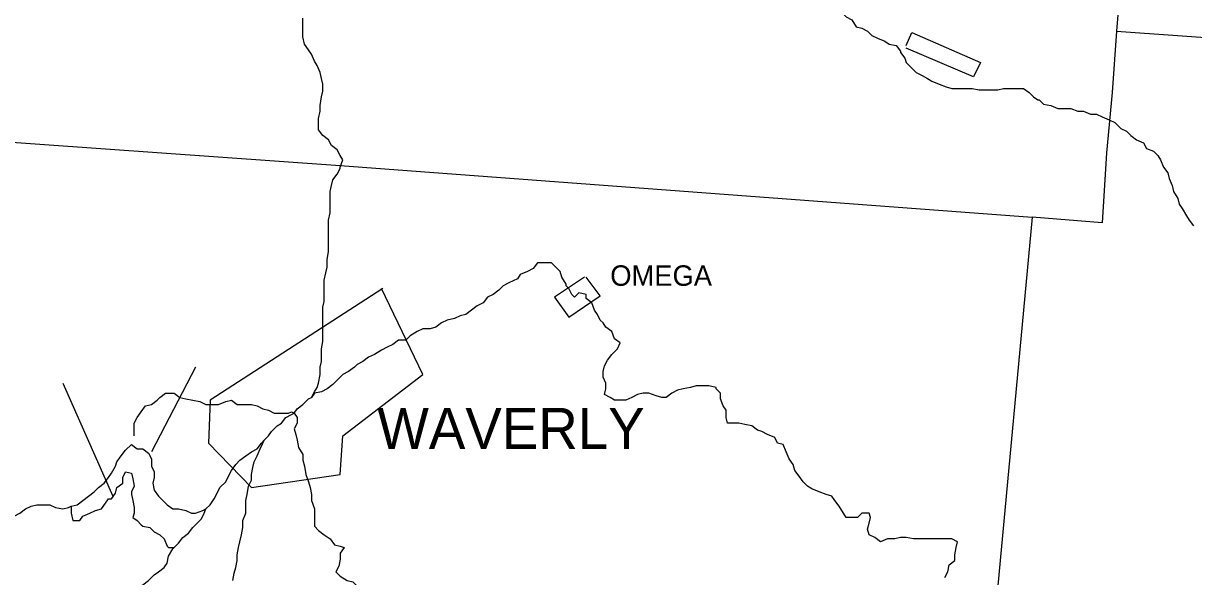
# Model space of a CAD drawing. Extents: x 0 to 34, y 0 to 22.
# Drawn here: x 5.85 to 6.966, y 18.089 to 18.617 of the extents above; entities that cross this region are included whole.
import ezdxf

# ---------------------------------------------------------------- set-up
doc = ezdxf.new("R2010")
doc.units = 0
doc.layers.add('Default', color=7, linetype='Continuous')

msp = doc.modelspace()

# ---------------------------------------------------------------- linework, layer by layer
at = {"layer": 'Default'}
for p, q in [((6.0144, 18.2889), (5.9722, 18.2085)), ((5.8876, 18.2739), (5.9354, 18.1662))]:
    msp.add_line(p, q, dxfattribs=at)
for points in [[(6.9566, 19.5337), (6.9457, 19.3646), (6.9197, 18.9774), (6.9088, 18.8056), (6.8925, 18.6093)], [(6.6048, 18.6529), (6.6089, 18.6475), (6.6143, 18.6448), (6.6184, 18.6379), (6.6212, 18.6339), (6.6266, 18.6339), (6.6307, 18.627), (6.6348, 18.6229), (6.6402, 18.6202), (6.6443, 18.6134), (6.6498, 18.612), (6.6552, 18.6093), (6.6593, 18.6052), (6.6648, 18.6025), (6.6716, 18.5998), (6.6757, 18.597), (6.6825, 18.5957), (6.6866, 18.5902), (6.6866, 18.5889)], [(6.1521, 18.4798), (6.1549, 18.4866), (6.1521, 18.4907), (6.1494, 18.4961), (6.144, 18.5002), (6.1412, 18.5057), (6.1358, 18.5098), (6.1317, 18.5152), (6.1317, 18.5207), (6.1317, 18.5261), (6.1331, 18.533), (6.1331, 18.5384), (6.1344, 18.5466), (6.1358, 18.552), (6.1358, 18.5589), (6.1344, 18.5643), (6.1331, 18.5698), (6.1303, 18.5766), (6.1276, 18.5807), (6.1249, 18.5875), (6.1221, 18.5916), (6.1181, 18.597), (6.1167, 18.6039), (6.1167, 18.6093), (6.1167, 18.6161), (6.1167, 18.6216)], [(6.1521, 18.4798), (6.1549, 18.4866), (6.1521, 18.4907), (6.1494, 18.4961), (6.144, 18.5002), (6.1412, 18.5057), (6.1358, 18.5098), (6.1317, 18.5152), (6.1317, 18.5207), (6.1317, 18.5261), (6.1331, 18.533), (6.1331, 18.5384), (6.1344, 18.5466), (6.1358, 18.552), (6.1358, 18.5589), (6.1344, 18.5643), (6.1331, 18.5698), (6.1303, 18.5766), (6.1276, 18.5807), (6.1249, 18.5875), (6.1221, 18.5916), (6.1181, 18.597), (6.1167, 18.6039), (6.1167, 18.6093), (6.1167, 18.6161), (6.1167, 18.6216)], [(6.6921, 18.5957), (6.6975, 18.6079), (6.763, 18.5793), (6.7561, 18.5657), (6.6921, 18.593)], [(6.8925, 18.6093), (6.8925, 18.6093), (6.8884, 18.5507), (6.8829, 18.4934), (6.8788, 18.4266), (6.812, 18.4321)], [(6.8925, 18.6093), (7.067, 18.597), (7.142, 18.593), (7.1761, 18.5902), (7.2892, 18.5834), (7.2838, 18.5261), (7.322, 18.5221), (7.3629, 18.5152), (7.4188, 18.5071), (7.4501, 18.5057), (7.5074, 18.5057), (7.5606, 18.5057), (7.6096, 18.4975), (7.6887, 18.4866), (7.6764, 18.3203)], [(6.6866, 18.5889), (6.6907, 18.5834), (6.6921, 18.5793), (6.6975, 18.5739), (6.7016, 18.5698), (6.7071, 18.567), (6.7125, 18.5643), (6.7166, 18.5616), (6.7234, 18.5589), (6.7302, 18.5561), (6.7357, 18.5548), (6.7411, 18.5548), (6.748, 18.5548), (6.7548, 18.5548), (6.7616, 18.5534), (6.7657, 18.5534), (6.7725, 18.5534), (6.7793, 18.5534), (6.7848, 18.5548), (6.7902, 18.5548), (6.7984, 18.5548), (6.8039, 18.5548), (6.8093, 18.5507), (6.8134, 18.5466), (6.8175, 18.5439), (6.8189, 18.5439)], [(4.8119, 18.5752), (4.9496, 18.567), (5.5209, 18.5261), (6.1521, 18.4811), (6.812, 18.4321)], [(6.8189, 18.5439), (6.8229, 18.5398), (6.8298, 18.5384), (6.8366, 18.5357), (6.842, 18.5357), (6.8489, 18.5357), (6.8557, 18.533), (6.8611, 18.533), (6.8679, 18.5302), (6.8734, 18.5302), (6.8788, 18.5275), (6.8857, 18.5248), (6.8857, 18.5248)], [(6.8857, 18.5248), (6.8911, 18.5221), (6.8966, 18.5166), (6.902, 18.5139), (6.9061, 18.5098), (6.9116, 18.5057), (6.9184, 18.503), (6.9211, 18.4975), (6.9279, 18.4948), (6.932, 18.4907), (6.9347, 18.4866), (6.9375, 18.4798), (6.9416, 18.4743), (6.9429, 18.4689), (6.9457, 18.4621), (6.947, 18.4566), (6.9511, 18.4498), (6.9525, 18.4443), (6.9552, 18.4402), (6.9593, 18.4334), (6.962, 18.4293), (6.9661, 18.4239)], [(6.1249, 18.2603), (6.1276, 18.2657), (6.1303, 18.2698), (6.1317, 18.2739), (6.1331, 18.2821), (6.1331, 18.2889), (6.1344, 18.2944), (6.1344, 18.3012), (6.1344, 18.3066), (6.1358, 18.3134), (6.1358, 18.3203), (6.1358, 18.3257), (6.1358, 18.3339), (6.1358, 18.3394), (6.1358, 18.3462), (6.1371, 18.3516), (6.1371, 18.3584), (6.1371, 18.3639), (6.1371, 18.3721), (6.1385, 18.3789), (6.1399, 18.3843), (6.1399, 18.3912), (6.1412, 18.3993), (6.1412, 18.4048), (6.1412, 18.4116), (6.1412, 18.4171), (6.1412, 18.4239), (6.1412, 18.4293), (6.1426, 18.4362), (6.1426, 18.443), (6.1426, 18.4498), (6.1426, 18.4566), (6.144, 18.4621), (6.1453, 18.4675), (6.1494, 18.473), (6.1521, 18.4784), (6.1521, 18.4784), (6.1521, 18.4798)], [(6.1249, 18.2603), (6.1276, 18.2657), (6.1303, 18.2698), (6.1317, 18.2739), (6.1331, 18.2821), (6.1331, 18.2889), (6.1344, 18.2944), (6.1344, 18.3012), (6.1344, 18.3066), (6.1358, 18.3134), (6.1358, 18.3203), (6.1358, 18.3257), (6.1358, 18.3339), (6.1358, 18.3394), (6.1358, 18.3462), (6.1371, 18.3516), (6.1371, 18.3584), (6.1371, 18.3639), (6.1371, 18.3721), (6.1385, 18.3789), (6.1399, 18.3843), (6.1399, 18.3912), (6.1412, 18.3993), (6.1412, 18.4048), (6.1412, 18.4116), (6.1412, 18.4171), (6.1412, 18.4239), (6.1412, 18.4293), (6.1426, 18.4362), (6.1426, 18.443), (6.1426, 18.4498), (6.1426, 18.4566), (6.144, 18.4621), (6.1453, 18.4675), (6.1494, 18.473), (6.1521, 18.4784), (6.1521, 18.4784), (6.1521, 18.4798)], [(6.812, 18.4321), (6.7875, 18.1662), (6.7561, 17.8322), (6.7657, 17.8281), (6.7561, 17.7163), (6.7343, 17.464), (6.733, 17.4327)], [(6.3676, 18.368), (6.3635, 18.3748), (6.3621, 18.3803), (6.3567, 18.3857), (6.3539, 18.3884), (6.3471, 18.3884), (6.3403, 18.3884), (6.3362, 18.383), (6.3308, 18.3803), (6.3239, 18.3775), (6.3212, 18.3734), (6.313, 18.3693), (6.3076, 18.3666), (6.3035, 18.3625), (6.298, 18.3584), (6.2926, 18.3557), (6.2885, 18.3503), (6.283, 18.3475), (6.2776, 18.3434), (6.2721, 18.3394), (6.2667, 18.338), (6.2612, 18.3353), (6.2544, 18.3339), (6.2489, 18.3312), (6.2435, 18.3271), (6.238, 18.3257), (6.2312, 18.3257), (6.2258, 18.323), (6.219, 18.3189), (6.2149, 18.3148), (6.208, 18.3148), (6.2026, 18.3107), (6.1971, 18.308), (6.1917, 18.3053), (6.1849, 18.3012), (6.1794, 18.2985), (6.174, 18.2944), (6.1685, 18.2916), (6.1658, 18.2889), (6.1603, 18.2848), (6.1549, 18.2821), (6.1494, 18.2766), (6.1453, 18.2725), (6.1399, 18.2685), (6.1344, 18.2657), (6.1276, 18.2644), (6.1249, 18.2603), (6.1249, 18.2603), (6.1249, 18.2603)], [(6.3853, 18.3748), (6.3567, 18.3557), (6.3703, 18.3366), (6.4003, 18.3571), (6.3867, 18.3748)], [(6.193, 18.3639), (6.0281, 18.2575), (6.0267, 18.2166), (6.0676, 18.1744), (6.1521, 18.1867), (6.1549, 18.2235), (6.2312, 18.2821), (6.1917, 18.3639)], [(6.4003, 18.3339), (6.3976, 18.3394), (6.3948, 18.3434), (6.3921, 18.3503), (6.3867, 18.3544), (6.3867, 18.3584), (6.3798, 18.3598), (6.3757, 18.3557), (6.373, 18.3584), (6.3703, 18.3639), (6.3676, 18.3666), (6.3676, 18.368)], [(6.4057, 18.2739), (6.403, 18.2794), (6.403, 18.2848), (6.4044, 18.2903), (6.4071, 18.2957), (6.4112, 18.3012), (6.4166, 18.3066), (6.4194, 18.3121), (6.4139, 18.3162), (6.4112, 18.323), (6.4057, 18.3271), (6.403, 18.3312), (6.4003, 18.3339)], [(6.5107, 18.2698), (6.5039, 18.2712), (6.4971, 18.2712), (6.4916, 18.2712), (6.4862, 18.2698), (6.4794, 18.2685), (6.4739, 18.2671), (6.4685, 18.2644), (6.463, 18.2603), (6.4589, 18.2603), (6.4535, 18.2616), (6.4466, 18.2644), (6.4412, 18.2644), (6.4357, 18.263), (6.4303, 18.2603), (6.4248, 18.2575), (6.4194, 18.2575), (6.4139, 18.2575), (6.4098, 18.2603), (6.4044, 18.263), (6.4057, 18.2685), (6.4057, 18.2725), (6.4057, 18.2739)], [(6.5216, 18.2357), (6.5203, 18.2412), (6.5203, 18.248), (6.5175, 18.2521), (6.5148, 18.2589), (6.5148, 18.2644), (6.5107, 18.2685), (6.5107, 18.2685), (6.5107, 18.2698)], [(5.9558, 18.2235), (5.9558, 18.2289), (5.9558, 18.2357), (5.9585, 18.2412), (5.9626, 18.2466), (5.9667, 18.2521), (5.9722, 18.2535), (5.9776, 18.2575), (5.9804, 18.2603), (5.9858, 18.2644), (5.9899, 18.2644), (5.994, 18.2644), (5.994, 18.2644)], [(5.994, 18.2644), (5.9994, 18.2603), (6.0049, 18.2589), (6.0117, 18.2575), (6.0185, 18.2562), (6.024, 18.2535), (6.0294, 18.2535), (6.0363, 18.2535), (6.0431, 18.2562), (6.0485, 18.2575), (6.054, 18.2535), (6.0594, 18.2535), (6.0676, 18.2535), (6.0731, 18.2521), (6.0785, 18.2494), (6.084, 18.248), (6.0894, 18.2453), (6.0949, 18.2453), (6.1031, 18.2453), (6.1058, 18.2466), (6.1085, 18.2453)], [(6.1085, 18.2453), (6.1112, 18.2494), (6.1167, 18.2535), (6.1221, 18.2589), (6.1249, 18.2603), (6.1249, 18.2603)], [(6.1085, 18.2453), (6.1112, 18.2494), (6.1167, 18.2535), (6.1221, 18.2589), (6.1249, 18.2603), (6.1249, 18.2603)], [(6.0799, 18.2194), (6.084, 18.2235), (6.0867, 18.2276), (6.0922, 18.233), (6.0962, 18.2357), (6.1003, 18.2412), (6.1058, 18.2439), (6.1085, 18.2453)], [(6.0799, 18.2194), (6.084, 18.2235), (6.0867, 18.2276), (6.0922, 18.233), (6.0962, 18.2357), (6.1003, 18.2412), (6.1058, 18.2439), (6.1085, 18.2453)], [(6.1085, 18.2453), (6.1112, 18.2412), (6.1112, 18.2357), (6.1085, 18.2303), (6.1099, 18.2248), (6.1112, 18.2194), (6.1126, 18.2126), (6.1167, 18.2057), (6.1167, 18.2003), (6.1181, 18.1948), (6.1194, 18.1867), (6.1194, 18.1867)], [(6.5775, 18.2085), (6.5748, 18.2153), (6.5693, 18.2166), (6.5666, 18.2221), (6.5598, 18.2248), (6.5544, 18.2276), (6.5503, 18.2289), (6.5448, 18.233), (6.538, 18.2344), (6.5325, 18.2357), (6.5257, 18.2357), (6.523, 18.2357), (6.5216, 18.2357)], [(5.8958, 18.1567), (5.9013, 18.158), (5.9067, 18.1621), (5.9122, 18.1662), (5.9176, 18.1703), (5.9217, 18.1744), (5.9272, 18.1785), (5.9313, 18.1839), (5.934, 18.188), (5.9381, 18.1948), (5.9394, 18.1989), (5.9435, 18.2044), (5.9476, 18.2098), (5.9531, 18.2153), (5.9531, 18.2153)], [(5.9531, 18.2153), (5.9585, 18.2112), (5.964, 18.2112), (5.9694, 18.2071), (5.9722, 18.2016), (5.9722, 18.1948), (5.9749, 18.1894), (5.9749, 18.1839), (5.9735, 18.1785), (5.9749, 18.1717), (5.979, 18.1662), (5.9831, 18.1621), (5.9872, 18.158), (5.9926, 18.1539), (5.9981, 18.1539), (6.0049, 18.1526), (6.0103, 18.1498), (6.0144, 18.1498), (6.0213, 18.1526), (6.024, 18.1539), (6.024, 18.1539)], [(6.024, 18.1539), (6.0281, 18.158), (6.0322, 18.1635), (6.0349, 18.1689), (6.0376, 18.1744), (6.0431, 18.1798), (6.0458, 18.1853), (6.0485, 18.1907), (6.0526, 18.1962), (6.0567, 18.2003), (6.0622, 18.2044), (6.0676, 18.2085), (6.0731, 18.2112), (6.0772, 18.2166), (6.0799, 18.2194)], [(6.0499, 18.0858), (6.0512, 18.0926), (6.0526, 18.098), (6.054, 18.1048), (6.054, 18.1103), (6.0553, 18.1171), (6.0567, 18.1226), (6.0581, 18.1294), (6.0594, 18.1362), (6.0594, 18.143), (6.0622, 18.1498), (6.0622, 18.1553), (6.0622, 18.1621), (6.0635, 18.1676), (6.0649, 18.1757), (6.0676, 18.1812), (6.0676, 18.1867), (6.069, 18.1935), (6.0703, 18.1989), (6.0731, 18.2044), (6.0758, 18.2112), (6.0785, 18.2166), (6.0799, 18.2194)], [(6.7289, 18.0885), (6.7316, 18.0939), (6.733, 18.1008), (6.7384, 18.1048), (6.7384, 18.1103), (6.7398, 18.1171), (6.7411, 18.1226), (6.7357, 18.1253), (6.7302, 18.1253), (6.7221, 18.1253), (6.7166, 18.1253), (6.7098, 18.1253), (6.7043, 18.1253), (6.6989, 18.1253), (6.6921, 18.1267), (6.6866, 18.1267), (6.6812, 18.1253), (6.6743, 18.1253), (6.6675, 18.1226), (6.6621, 18.1267), (6.6566, 18.1294), (6.6552, 18.1348), (6.6566, 18.1403), (6.658, 18.1457), (6.6566, 18.1498), (6.6498, 18.1498), (6.6457, 18.1457), (6.6402, 18.1457), (6.6348, 18.1457), (6.6321, 18.1498), (6.628, 18.1567), (6.6239, 18.1621), (6.6212, 18.1662), (6.6157, 18.1676), (6.6089, 18.1703), (6.6021, 18.173), (6.598, 18.1757), (6.5939, 18.1798), (6.5898, 18.1853), (6.5857, 18.1907), (6.5843, 18.1962), (6.5803, 18.2016), (6.5775, 18.2085), (6.5775, 18.2085), (6.5775, 18.2085), (6.5775, 18.2085)], [(5.934, 18.1635), (5.9381, 18.1689), (5.9394, 18.1744), (5.9449, 18.1785), (5.9449, 18.1839), (5.9476, 18.1894), (5.9531, 18.188), (5.9544, 18.1826), (5.9558, 18.1757), (5.9531, 18.1703), (5.9531, 18.1689), (5.9531, 18.1676)], [(6.1194, 18.1867), (6.1221, 18.1798), (6.1235, 18.1744), (6.1249, 18.1676), (6.1249, 18.1621), (6.1276, 18.1539), (6.1276, 18.1498), (6.1276, 18.143), (6.1276, 18.1376), (6.1317, 18.1335), (6.1371, 18.1294), (6.1426, 18.1253), (6.1467, 18.1198), (6.1521, 18.1185), (6.1562, 18.1171), (6.1521, 18.1117), (6.1521, 18.1062), (6.1508, 18.0994), (6.1481, 18.0939), (6.1481, 18.0939), (6.1481, 18.0939)], [(5.8358, 18.143), (5.8413, 18.1471), (5.8467, 18.1498), (5.8522, 18.1539), (5.8576, 18.1567), (5.8631, 18.158), (5.8699, 18.158), (5.8754, 18.158), (5.8808, 18.1553), (5.8876, 18.1539), (5.8931, 18.1553), (5.8958, 18.1567)], [(5.8958, 18.1567), (5.8958, 18.1498), (5.8972, 18.143), (5.904, 18.143), (5.9067, 18.1471), (5.9135, 18.1498), (5.919, 18.1526), (5.9245, 18.1539), (5.9285, 18.1594), (5.9313, 18.1635), (5.934, 18.1635)], [(5.9531, 18.1676), (5.9544, 18.1621), (5.9558, 18.1553), (5.9558, 18.1498), (5.9544, 18.1457), (5.9585, 18.143), (5.9626, 18.1389), (5.964, 18.1376), (5.964, 18.1376)], [(5.994, 18.1171), (5.9981, 18.1212), (6.0022, 18.1267), (6.0076, 18.1308), (6.0117, 18.1362), (6.0158, 18.1403), (6.0199, 18.1444), (6.0226, 18.1498), (6.024, 18.1539)], [(5.964, 18.1376), (5.9708, 18.1362), (5.9749, 18.1321), (5.9804, 18.1294), (5.9844, 18.1253), (5.9872, 18.1185), (5.9885, 18.1171), (5.994, 18.1171), (5.994, 18.1171)], [(5.9585, 18.0789), (5.964, 18.0817), (5.9694, 18.0858), (5.9749, 18.0912), (5.979, 18.0939), (5.9844, 18.098), (5.9872, 18.1021), (5.9885, 18.1089), (5.9926, 18.1158), (5.994, 18.1171)], [(6.1481, 18.0939), (6.1521, 18.0898), (6.159, 18.0858), (6.1644, 18.0844), (6.1685, 18.0803), (6.174, 18.0776), (6.1767, 18.0721), (6.178, 18.0667), (6.1821, 18.0612), (6.1849, 18.0558), (6.189, 18.0503), (6.1903, 18.0449), (6.1903, 18.038), (6.1903, 18.0312), (6.1903, 18.0258), (6.1903, 18.019), (6.1917, 18.0135)]]:
    msp.add_lwpolyline(points, dxfattribs=at)

# ---------------------------------------------------------------- texts
for s, height, p in [('OMEGA', 0.0195, (6.4098, 18.3666)), ('WAVERLY', 0.039, (6.1876, 18.2112))]:
    msp.add_text(s, height=height, dxfattribs=at).set_placement(p)

doc.saveas('drawing.dxf')
